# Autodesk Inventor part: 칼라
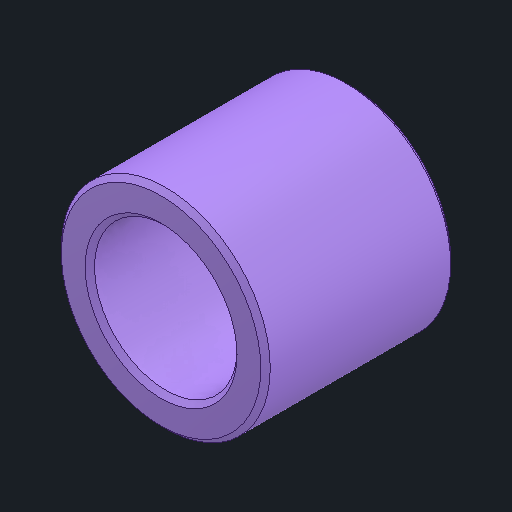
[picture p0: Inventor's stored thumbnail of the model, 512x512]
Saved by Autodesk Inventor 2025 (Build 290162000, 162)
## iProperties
Created: 2025-08
Part Number: 칼라
Material: 스테인리스강
Document SubType Name: Modeling
Designer: infra11
Density: 8.08 g/cm^3
Appearance: 기본값
Author: jhkim
Sending System: Autodesk Inventor 2026
Preprocessor: ST-DEVELOPER v20.1
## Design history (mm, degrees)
feature "솔리드1"
node "솔리드2"
